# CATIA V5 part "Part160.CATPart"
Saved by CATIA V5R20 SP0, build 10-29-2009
Part number: FA 105700-3
Revision: ANY
Definition: UNKNOWN
Nomenclature: FA 105700-3
Source: Unknown
Bounding box of the stored display mesh (mm): x -2.687 to 2.687, y -2.475 to 2.475, z -2.5 to 2.5
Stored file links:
  C:\Users\Utente\Desktop\IO LAVORO\3D X SITO CF\CUMSA\3D files FA\FA 105712-20\Part160.CATPart
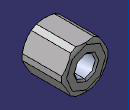
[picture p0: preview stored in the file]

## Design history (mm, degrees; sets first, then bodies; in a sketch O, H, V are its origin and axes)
Body1 "Chaflán4" (main body)
  Solid1: solid without history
